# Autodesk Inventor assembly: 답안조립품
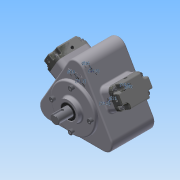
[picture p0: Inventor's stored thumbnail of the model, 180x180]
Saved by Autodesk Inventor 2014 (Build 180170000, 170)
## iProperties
Created: 2015-06
Part Number: 답안조립품
Document SubType Name: Assembly
Designer: MYHOME
Mass: 5318.58 g
Surface Area: 2414.93 cm^2
Volume: 1564.62 cm^3
Density: 3.39928 g/cm^3
Author: MYHOME
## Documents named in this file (20)
- C:\Documents and Settings\MYHOME\바탕 화면\350605V1046\답안조립품.iam
- C:\Documents and Settings\MYHOME\바탕 화면\350605V1046\본체.ipt
- C:\Documents and Settings\MYHOME\바탕 화면\350605V1046\베어링 NA 4904.ipt
- 베어링 NA 4904.ipt
- C:\Documents and Settings\MYHOME\바탕 화면\350605V1046\앞커버.ipt
- C:\Documents and Settings\MYHOME\바탕 화면\350605V1046\오일실.ipt
- 오일실.ipt
- C:\Documents and Settings\MYHOME\바탕 화면\350605V1046\편심축.ipt
- C:\Documents and Settings\MYHOME\바탕 화면\350605V1046\M6x0.7x20.ipt
- M6x0.7x20.ipt
- C:\Documents and Settings\MYHOME\바탕 화면\350605V1046\헤더커버.ipt
- 헤더커버.ipt
- C:\Documents and Settings\MYHOME\바탕 화면\350605V1046\부시.ipt
- C:\Documents and Settings\MYHOME\바탕 화면\350605V1046\M4x0.5x16.ipt
- M4x0.5x16.ipt
- C:\Documents and Settings\MYHOME\바탕 화면\350605V1046\슬라이드.ipt
- C:\Documents and Settings\MYHOME\바탕 화면\350605V1046\스프링1.ipt
- C:\Documents and Settings\MYHOME\바탕 화면\350605V1046\스프링2.ipt
- C:\Documents and Settings\MYHOME\바탕 화면\350605V1046\스프링3.ipt
- C:\Documents and Settings\MYHOME\바탕 화면\350605V1046\스프링4.ipt
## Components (14 placed, 3 different names)
1. 헤더커버:1
2. 헤더커버:2
3. M4x0.5x16:1
4. M4x0.5x16:2
5. M4x0.5x16:3
6. M4x0.5x16:4
7. M4x0.5x16:5
8. M4x0.5x16:6
9. M4x0.5x16:7
10. M4x0.5x16:8
11. M6x0.7x20:1
12. M6x0.7x20:2
13. M6x0.7x20:3
14. M6x0.7x20:4
